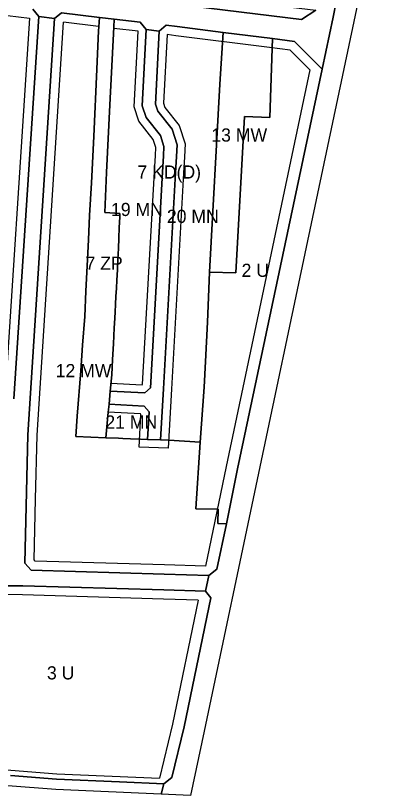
# Model space of a CAD drawing. Extents: x 7424258 to 7426021, y 5551671 to 5553193.
# Drawn here: x 7425590 to 7425881, y 5551671 to 5552263 of the extents above; entities that cross this region are included whole.
import ezdxf

# ---------------------------------------------------------------- set-up
doc = ezdxf.new("R2010")
doc.units = 0
for name, color, linetype in [('linie_rozgraniczajace', 7, 'Continuous'), ('linie_zabudowy_nieprzekraczalne', 7, 'Continuous'), ('oznaczenia_przeznaczen', 7, 'Continuous')]:
    doc.layers.add(name, color=color, linetype=linetype)

msp = doc.modelspace()

# ---------------------------------------------------------------- linework, layer by layer
at = {"layer": 'linie_rozgraniczajace'}
for points in [[(7425881.23, 5552423.32), (7425846.58, 5552258.58), (7425810.39, 5552087.13), (7425774.23, 5551915.45), (7425732.96, 5551719.61), (7425722.66, 5551670.86), (7425700.45, 5551671.82), (7425702.36, 5551679.74), (7425708.52, 5551684.38), (7425717.84, 5551723.02), (7425738.13, 5551820.89), (7425734.14, 5551825.91), (7425736.62, 5551837.84), (7425742.63, 5551842.59), (7425750.02, 5551877.19), (7425758.42, 5551918.77), (7425822.49, 5552222.22), (7425830.86, 5552261.88), (7425833.28, 5552273.38)], [(7425833.28, 5552273.38), (7425830.86, 5552261.88), (7425822.49, 5552222.22), (7425801.61, 5552243.4), (7425784.85, 5552245.52), (7425747.45, 5552250.24), (7425712.46, 5552254.66), (7425704.19, 5552255.64), (7425698.96, 5552251.23), (7425689.01, 5552252.4), (7425684.38, 5552257.96), (7425664.74, 5552260.28), (7425653.53, 5552261.6), (7425624.71, 5552265.13), (7425619.43, 5552260.74), (7425607.51, 5552262.2), (7425602.87, 5552267.8)], [(7425701.37, 5552272.89), (7425807, 5552259.94), (7425817.72, 5552267.22)], [(7425602.87, 5552267.8), (7425607.51, 5552262.2), (7425588.61, 5551971.9)], [(7425588.61, 5551971.9), (7425607.51, 5552262.2), (7425619.43, 5552260.74), (7425599.22, 5551944.59), (7425596.79, 5551847.15), (7425601.68, 5551841.86), (7425702.75, 5551838.87), (7425736.62, 5551837.84), (7425734.14, 5551825.91), (7425702.39, 5551826.87), (7425595.25, 5551830.04), (7425581.02, 5551830.07)], [(7425581.02, 5551830.07), (7425595.25, 5551830.04), (7425702.39, 5551826.87), (7425734.14, 5551825.91), (7425738.13, 5551820.89), (7425717.84, 5551723.02), (7425708.52, 5551684.38), (7425702.36, 5551679.74), (7425668.66, 5551681.2), (7425620.82, 5551683.29), (7425586.01, 5551685.98)], [(7425586.01, 5551685.98), (7425620.82, 5551683.29), (7425668.66, 5551681.2), (7425702.36, 5551679.74), (7425700.45, 5551671.82), (7425620.33, 5551675.3), (7425550.46, 5551680.7)]]:
    msp.add_lwpolyline(points, dxfattribs=at)
for points in [[(7425701.37, 5552272.89), (7425701.91, 5552281.4), (7425750.16, 5552275.48), (7425817.72, 5552267.22), (7425807, 5552259.94)], [(7425619.43, 5552260.74), (7425624.71, 5552265.13), (7425653.53, 5552261.6), (7425653.03, 5552254.35), (7425652.8, 5552251.28), (7425651.44, 5552222.41), (7425649.16, 5552171.21), (7425647.46, 5552136.03), (7425646.06, 5552111.25), (7425645.15, 5552092.79), (7425644.31, 5552073.09), (7425643.24, 5552053.78), (7425642.31, 5552034.48), (7425640.7, 5552012.84), (7425639.26, 5551993.31), (7425636.67, 5551958.7), (7425635.51, 5551943.26), (7425658.36, 5551942.36), (7425667.98, 5551942.01), (7425671.26, 5551941.89), (7425676.97, 5551941.67), (7425684.71, 5551941.37), (7425689.95, 5551941.08), (7425699.95, 5551940.83), (7425706.3, 5551940.63), (7425730.03, 5551939), (7425726.79, 5551888.46), (7425743.57, 5551888.08), (7425743.34, 5551877.34), (7425750.02, 5551877.19), (7425742.63, 5551842.59), (7425736.62, 5551837.84), (7425702.75, 5551838.87), (7425601.68, 5551841.86), (7425596.79, 5551847.15), (7425599.22, 5551944.59)], [(7425658.36, 5551942.36), (7425635.51, 5551943.26), (7425636.67, 5551958.7), (7425639.26, 5551993.31), (7425640.7, 5552012.84), (7425642.31, 5552034.48), (7425643.24, 5552053.78), (7425644.31, 5552073.09), (7425645.15, 5552092.79), (7425646.06, 5552111.25), (7425647.46, 5552136.03), (7425649.16, 5552171.21), (7425651.44, 5552222.41), (7425652.8, 5552251.28), (7425653.03, 5552254.35), (7425653.53, 5552261.6), (7425664.74, 5552260.28), (7425664.39, 5552254.27), (7425661.42, 5552195.24), (7425658.92, 5552143.73), (7425657.71, 5552113.53), (7425669.06, 5552112.75), (7425668.94, 5552110), (7425668.58, 5552102.01), (7425668.21, 5552094.01), (7425667.86, 5552086.02), (7425667.49, 5552078.03), (7425667.16, 5552070.81), (7425667.13, 5552070.04), (7425666.67, 5552062.06), (7425666.38, 5552055.92), (7425666.06, 5552049.77), (7425665.74, 5552043.78), (7425665.42, 5552037.79), (7425664.97, 5552029.15), (7425664.79, 5552025.8), (7425664.14, 5552013.83), (7425663.5, 5552001.84), (7425663.19, 5551996.04), (7425662.88, 5551990.25), (7425661.72, 5551977.91), (7425660.78, 5551967.94), (7425660.21, 5551961.97)], [(7425661.72, 5551977.91), (7425662.88, 5551990.25), (7425663.19, 5551996.04), (7425663.5, 5552001.84), (7425664.14, 5552013.83), (7425664.79, 5552025.8), (7425664.97, 5552029.15), (7425665.42, 5552037.79), (7425665.74, 5552043.78), (7425666.06, 5552049.77), (7425666.38, 5552055.92), (7425666.67, 5552062.06), (7425667.13, 5552070.04), (7425667.16, 5552070.81), (7425667.49, 5552078.03), (7425667.86, 5552086.02), (7425668.21, 5552094.01), (7425668.58, 5552102.01), (7425668.94, 5552110), (7425669.06, 5552112.75), (7425657.71, 5552113.53), (7425658.92, 5552143.73), (7425661.42, 5552195.24), (7425664.39, 5552254.27), (7425664.74, 5552260.28), (7425684.38, 5552257.96), (7425689.01, 5552252.4), (7425685.99, 5552194.47), (7425688.89, 5552185.59), (7425699.74, 5552171.88), (7425702.44, 5552163.5), (7425702.06, 5552156.51), (7425701.36, 5552144.12), (7425692.16, 5551980.21), (7425688.03, 5551976.53)], [(7425699.95, 5551940.83), (7425702.14, 5551979.64), (7425711.34, 5552143.56), (7425712.04, 5552155.96), (7425712.53, 5552164.8), (7425708.7, 5552176.67), (7425697.84, 5552190.39), (7425696.08, 5552195.8), (7425698.96, 5552251.23), (7425704.19, 5552255.64), (7425712.46, 5552254.66), (7425747.45, 5552250.24), (7425744.92, 5552210.95), (7425737.17, 5552068.17), (7425735.66, 5552030.2), (7425734.04, 5552000.25), (7425732.91, 5551980.92), (7425730.03, 5551939), (7425706.3, 5551940.63)], [(7425660.78, 5551967.94), (7425661.72, 5551977.91), (7425688.03, 5551976.53), (7425692.16, 5551980.21), (7425701.36, 5552144.12), (7425702.06, 5552156.51), (7425702.44, 5552163.5), (7425699.74, 5552171.88), (7425688.89, 5552185.59), (7425685.99, 5552194.47), (7425689.01, 5552252.4), (7425698.96, 5552251.23), (7425696.08, 5552195.8), (7425697.84, 5552190.39), (7425708.7, 5552176.67), (7425712.53, 5552164.8), (7425712.04, 5552155.96), (7425711.34, 5552143.56), (7425702.14, 5551979.64), (7425699.95, 5551940.83), (7425689.95, 5551941.08), (7425691.14, 5551962.23), (7425687.37, 5551966.45)], [(7425737.17, 5552068.17), (7425744.92, 5552210.95), (7425747.45, 5552250.24), (7425784.85, 5552245.52), (7425782.96, 5552185.57), (7425763.65, 5552186.42), (7425756.97, 5552067.66)], [(7425730.03, 5551939), (7425732.91, 5551980.92), (7425734.04, 5552000.25), (7425735.66, 5552030.2), (7425737.17, 5552068.17), (7425756.97, 5552067.66), (7425763.65, 5552186.42), (7425782.96, 5552185.57), (7425784.85, 5552245.52), (7425801.61, 5552243.4), (7425822.49, 5552222.22), (7425758.42, 5551918.77), (7425750.02, 5551877.19), (7425743.34, 5551877.34), (7425743.57, 5551888.08), (7425726.79, 5551888.46)], [(7425658.36, 5551942.36), (7425660.21, 5551961.97), (7425660.78, 5551967.94), (7425687.37, 5551966.45), (7425691.14, 5551962.23), (7425689.95, 5551941.08), (7425684.71, 5551941.37), (7425676.97, 5551941.67), (7425671.26, 5551941.89), (7425667.98, 5551942.01)]]:
    msp.add_lwpolyline(points, close=True, dxfattribs=at)
at = {"layer": 'linie_zabudowy_nieprzekraczalne'}
for points in [[(7425447.48, 5552280.34), (7425458.26, 5552278.45), (7425600.41, 5552261.05)], [(7425600.41, 5552261.05), (7425579.82, 5551944.61), (7425579, 5551903.58), (7425578, 5551902.64), (7425551.12, 5551903.36), (7425550.31, 5551903.38)], [(7425733.92, 5551844.93), (7425702.96, 5551845.86), (7425604.82, 5551848.77), (7425603.86, 5551849.82), (7425605, 5551895.7), (7425606.22, 5551944.42), (7425616.35, 5552102.77), (7425626.26, 5552257.88)], [(7425653.05, 5552254.61), (7425652.7, 5552254.65), (7425626.26, 5552257.88)], [(7425704.83, 5552248.51), (7425702.13, 5552196.6), (7425703.21, 5552193.27), (7425714.08, 5552179.54), (7425718.58, 5552165.59), (7425718.03, 5552155.62), (7425717.33, 5552143.23), (7425708.13, 5551979.31), (7425705.61, 5551934.63), (7425683.62, 5551935.39), (7425685.01, 5551960.09), (7425684.55, 5551960.6), (7425660.22, 5551961.97)], [(7425662.28, 5551983.89), (7425685.88, 5551982.64), (7425686.31, 5551983.02), (7425695.37, 5552144.46), (7425696.07, 5552156.85), (7425696.39, 5552162.72), (7425694.37, 5552169.01), (7425683.52, 5552182.71), (7425679.95, 5552193.67), (7425682.93, 5552251.09)], [(7425682.93, 5552251.09), (7425664.34, 5552253.28)], [(7425813.18, 5552221.69), (7425798.33, 5552236.76), (7425782.73, 5552238.73), (7425711.6, 5552247.72), (7425704.83, 5552248.51)], [(7425813.18, 5552221.69), (7425749.61, 5551920.6), (7425733.92, 5551844.93)], [(7425728.57, 5551819.08), (7425702.18, 5551819.88), (7425595.14, 5551823.05), (7425561.91, 5551823.4), (7425546.48, 5551823.52), (7425506.61, 5551824.63)], [(7425728.57, 5551819.08), (7425709.06, 5551724.99), (7425699.15, 5551683.89)], [(7425322.9, 5551696.06), (7425376.71, 5551700.55), (7425409.58, 5551701.29), (7425462.96, 5551702.5), (7425509.54, 5551697.33), (7425551.59, 5551692.65), (7425562.48, 5551691.81), (7425586.32, 5551689.97), (7425621.06, 5551687.28), (7425699.15, 5551683.89)]]:
    msp.add_lwpolyline(points, dxfattribs=at)

# ---------------------------------------------------------------- texts
at = {"layer": 'oznaczenia_przeznaczen'}
for s, p in [('13 MW', (7425738.47, 5552167.3)), ('7 KD(D)', (7425682.33, 5552139.21)), ('19 MN', (7425662.31, 5552110.77)), ('20 MN', (7425704.71, 5552105.56)), ('7 ZP', (7425642.97, 5552069.94)), ('2 U', (7425761.42, 5552064.56)), ('12 MW', (7425620.31, 5551988.4)), ('21 MN', (7425657.99, 5551949.33)), ('3 U', (7425613.65, 5551758.91))]:
    msp.add_text(s, height=10, dxfattribs=at).set_placement(p)

doc.saveas('drawing.dxf')
